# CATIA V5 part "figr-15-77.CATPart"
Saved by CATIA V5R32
Part number: Part1
Bounding box of the stored display mesh (mm): x -59.264 to 75.079, y -54.323 to 58.486, z 0 to 41.762
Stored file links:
  D:\PROJECTS\Project 2022\CATIA V5 6R 2022\Resources\Part Files\c15_catia_v5_6r2022_prt\figr-15-77.CATPart
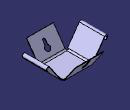
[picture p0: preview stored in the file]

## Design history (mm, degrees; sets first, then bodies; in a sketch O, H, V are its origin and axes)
SheetMetalParameters1: Thickness 1, BendRadius 5, KFactor 0.5 {= log(min(100,max(20*SheetMetalParameters1.BendRadius,SheetMetalParameters1.Thickness)/SheetMetalParameters1.Thickness))/log(100)/2}, ReliefRadialLength 1, ReliefAxialLength 2, MinimumBendRadius 0
Body1 (main body)
  Sketch1 on xy-plane, origin (0, 0, 0), H (1, 0, 0), V (0, 1, 0)
    line L1 (-24.5181, 30.1968) -> (40.3332, 30.1968)
    line L2 (40.3332, 30.1968) -> (40.3332, -26.0343)
    line L3 (40.3332, -26.0343) -> (-24.5181, -26.0343)
    line L4 (-24.5181, -26.0343) -> (-24.5181, 30.1968)
    horizontal: L1 H, L3 H
    vertical: L2 V, L4 V
  Wall1: Thickness 1, Profile Sketch1
  d_NewWallOnEdge1: NewWallOnEdge_Edge edge [face of Wall1 | face of Wall1], NewWallOnEdge_Length 40.2311, NewWallOnEdge_HeightLimitOffset 0, NewWallOnEdge_WidthOffset1 0, NewWallOnEdge_WidthOffset2 0, NewWallOnEdge_Angle 125, NewWallOnEdge_BendRadiusValue 5 {= SheetMetalParameters1.BendRadius}, NewWallOnEdge_BendTable SheetMetalParameters1, KFacteur 0.5 {= log(min(100,max(20*d_NewWallOnEdge1.Radius,SheetMetalParameters1.Thickness)/SheetMetalParameters1.Thickness))/log(100)/2}
  d_NewWallOnEdge2: NewWallOnEdge_Edge edge [face of Wall1 | face of Wall1], NewWallOnEdge_Length 40.2311, NewWallOnEdge_HeightLimitOffset 0, NewWallOnEdge_WidthOffset1 0, NewWallOnEdge_WidthOffset2 0, NewWallOnEdge_Angle 125, NewWallOnEdge_BendRadiusValue 5 {= SheetMetalParameters1.BendRadius}, NewWallOnEdge_BendTable SheetMetalParameters1, KFacteur 0.5 {= log(min(100,max(20*d_NewWallOnEdge2.Radius,SheetMetalParameters1.Thickness)/SheetMetalParameters1.Thickness))/log(100)/2}
  d_NewWallOnEdge3: NewWallOnEdge_Edge edge [face of Wall1 | face of Wall1], NewWallOnEdge_Length 40.2311, NewWallOnEdge_HeightLimitOffset 0, NewWallOnEdge_WidthOffset1 0, NewWallOnEdge_WidthOffset2 0, NewWallOnEdge_Angle 125, NewWallOnEdge_BendRadiusValue 5 {= SheetMetalParameters1.BendRadius}, NewWallOnEdge_BendTable SheetMetalParameters1, KFacteur 0.5 {= log(min(100,max(20*d_NewWallOnEdge3.Radius,SheetMetalParameters1.Thickness)/SheetMetalParameters1.Thickness))/log(100)/2}
  d_NewWallOnEdge4: NewWallOnEdge_Edge edge [face of Wall1 | face of Wall1], NewWallOnEdge_Length 40.2311, NewWallOnEdge_HeightLimitOffset 0, NewWallOnEdge_WidthOffset1 0, NewWallOnEdge_WidthOffset2 0, NewWallOnEdge_Angle 125, NewWallOnEdge_BendRadiusValue 5 {= SheetMetalParameters1.BendRadius}, NewWallOnEdge_BendTable SheetMetalParameters1, KFacteur 0.5 {= log(min(100,max(20*d_NewWallOnEdge4.Radius,SheetMetalParameters1.Thickness)/SheetMetalParameters1.Thickness))/log(100)/2}
  Sketch2 on face of d_NewWallOnEdge4, origin (0, -16.9994, -11.9031), H (-1, 0, 0), V (0, -0.5736, 0.8192)
    construction line L1 (-8.3417, 33.0355) -> (-8.3417, 47.6528)
    line L2 (-5.6402, 47.6528) -> (-5.6402, 38.4491)
    line L3 (-11.0431, 38.4491) -> (-11.0431, 47.6528)
    arc A1 centre (-8.3417, 33.0355) radius 6.0503 from (-5.6402, 38.4491) to (-11.0431, 38.4491) cw
    arc A2 centre (-8.3417, 47.6528) radius 2.7015 from (-11.0431, 47.6528) to (-5.6402, 47.6528) cw
    radius A1 = 6.0503
    radius A2 = 2.7015
    vertical: L1 V
    tangency: A2 L2, A2 L3
    parallelism: L2 L3, L2 L1
  CutOut1: Direction Sketch2, EndLimit through (limit type 3), Orientation false, Profile Sketch2, StartLimit through (limit type 2)
  Sketch3 on face of d_NewWallOnEdge2, origin (0, 19.7925, -13.8589), H (1, 0, 0), V (0, 0.5736, 0.8192)
    construction line L1 (6.0153, 41.1403) -> (6.0153, 57.8706)
    line L2 (8.7383, 57.8706) -> (8.7383, 46.3808)
    line L3 (3.2923, 46.3808) -> (3.2923, 57.8706)
    arc A1 centre (6.0153, 41.1403) radius 5.9058 from (8.7383, 46.3808) to (3.2923, 46.3808) cw
    arc A2 centre (6.0153, 57.8706) radius 2.723 from (3.2923, 57.8706) to (8.7383, 57.8706) cw
    radius A1 = 5.9058
    radius A2 = 2.723
    vertical: L1 V
    tangency: A2 L2, A2 L3
    parallelism: L2 L3, L2 L1
  CutOut2: Direction Sketch3, EndLimit through (limit type 3), Orientation true, Profile Sketch3, StartLimit through (limit type 2)
  Flange1: Angle 90, Length 5, Radius 3, KFacteur 0.444538 {= log(min(100,max(20*Flange1.Radius,SheetMetalParameters1.Thickness)/SheetMetalParameters1.Thickness))/log(100)/2}, Guide edge [face of d_NewWallOnEdge1 | face of d_NewWallOnEdge1]
  Flange2: Angle 90, Length 5, Radius 3, KFacteur 0.444538 {= log(min(100,max(20*Flange2.Radius,SheetMetalParameters1.Thickness)/SheetMetalParameters1.Thickness))/log(100)/2}, Guide edge [face of d_NewWallOnEdge3 | face of d_NewWallOnEdge3]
